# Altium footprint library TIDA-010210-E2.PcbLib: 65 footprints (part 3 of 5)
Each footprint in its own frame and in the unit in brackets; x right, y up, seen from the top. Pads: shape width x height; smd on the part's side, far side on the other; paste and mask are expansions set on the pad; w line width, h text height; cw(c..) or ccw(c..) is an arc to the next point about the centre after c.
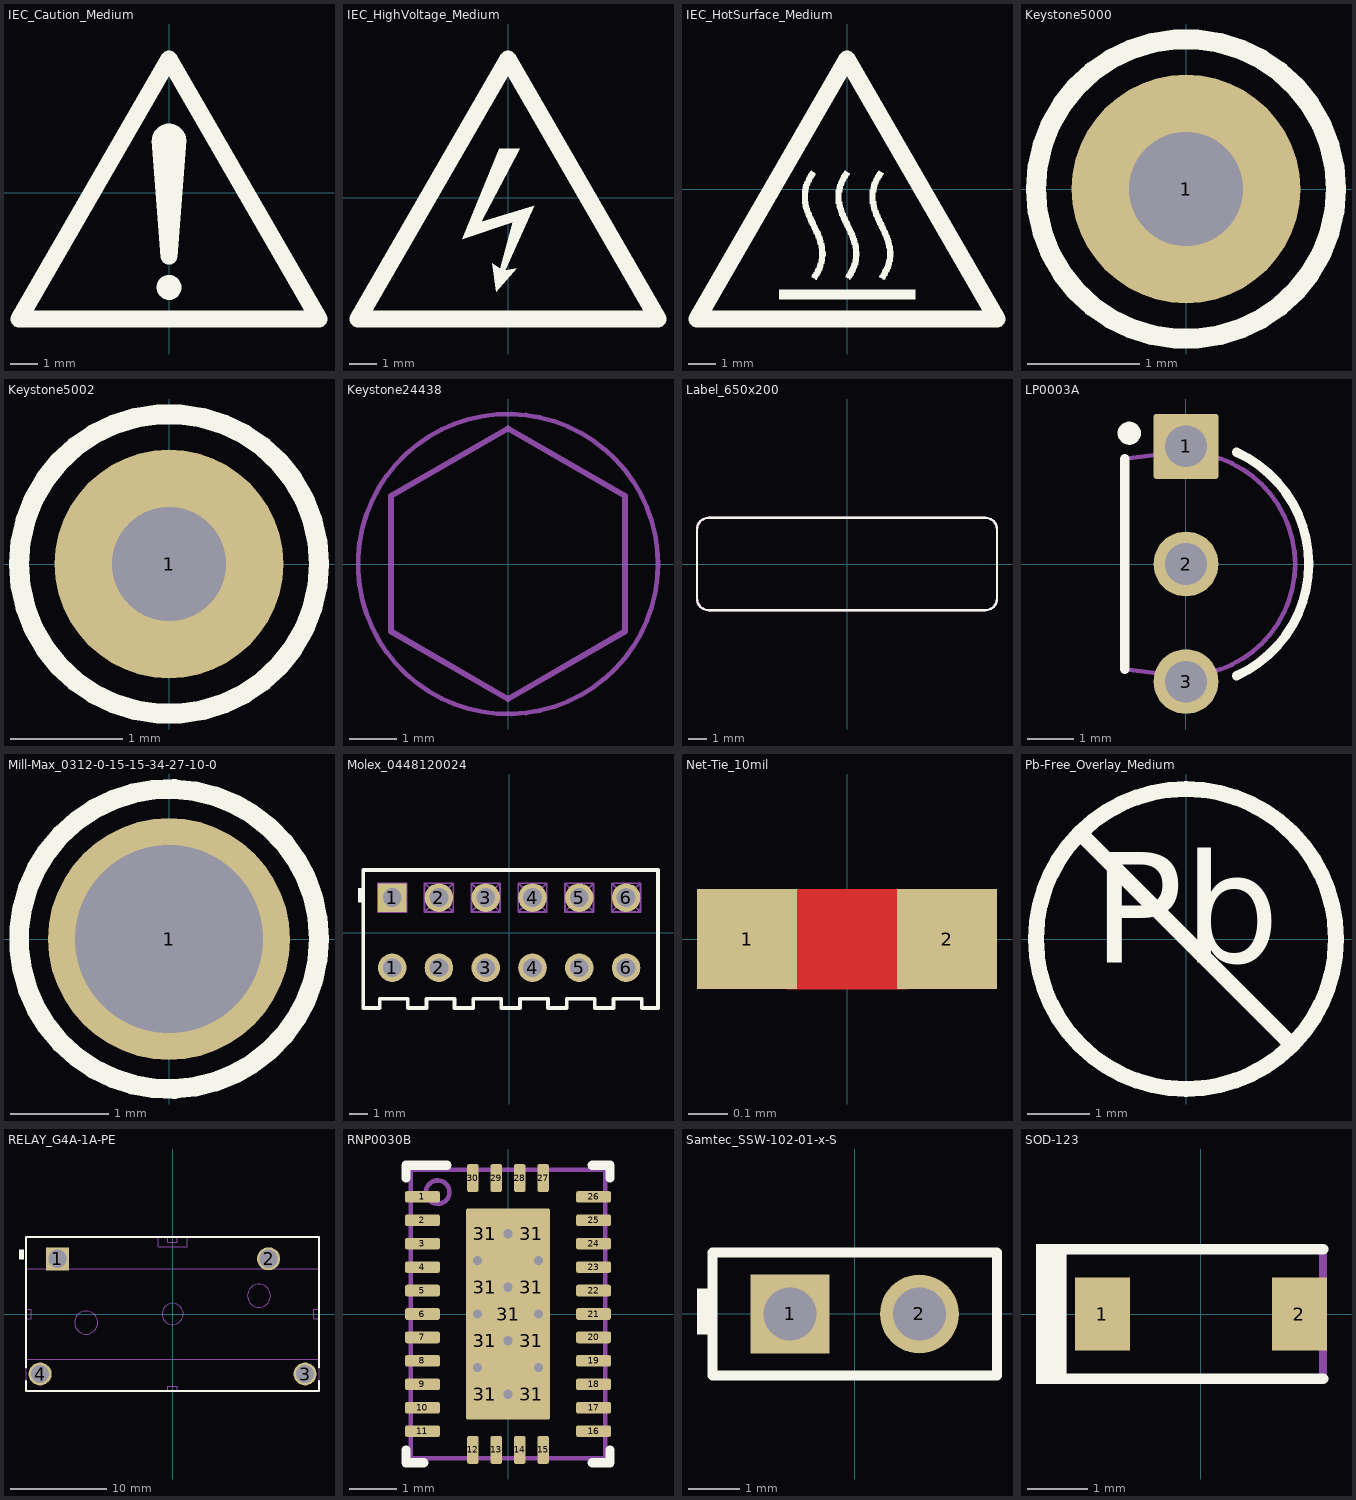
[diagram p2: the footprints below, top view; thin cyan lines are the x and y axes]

## IEC_Caution_Medium [mm]
height 27
Top Overlay:
  circle w0.457: c0,-3.48 r0.229
  circle w0.635: c0,1.905 r0.318
  circle w0.305: c0,-2.337 r0.152
  region: -0.635,1.93 0.635,1.93 0.305,-2.362 -0.305,-2.362
  lines w0.635: -5.512,-4.635 0,4.911 5.512,-4.635 -5.512,-4.635

## IEC_HighVoltage_Medium [mm]
height 27
Top Overlay:
  region: -0.33,1.803 0.432,1.803 -0.991,-0.889 0.965,-0.305 -0.102,-2.667 0.33,-2.591 -0.432,-3.454 -0.584,-2.413 -0.279,-2.616 0.178,-0.914 -1.676,-1.524
  lines w0.635: -5.512,-4.458 0,5.089 5.512,-4.458 -5.512,-4.458

## IEC_HotSurface_Medium [mm]
height 27
Top Overlay:
  drawing of 7 lines, arcs and shapes, not listed

## Keystone5000 [mil] "For Keystone 500x miniature loop terminals"
height 181.1
pads (1):
  round 80 hole 40: 1(0,0)
Top Overlay:
  circle w7: c0,0 r52.5
Mechanical 5:
  circle w3.94: c0,0 r52.5
  text ".Designator" at -92.97,-15 h18
3D body "Keystone_5000.stp": height 181.97, standoff -118.11, extent -49,-49 49.04,49.24

## Keystone5002 [mil] "For Keystone 500x miniature loop terminals"
height 181.1
pads (1):
  round 80 hole 40: 1(0,0)
Top Overlay:
  circle w7: c0,0 r52.5
Mechanical 5:
  circle w3.94: c0,0 r52.5
  text ".Designator" at -92.97,-15 h18
3D body "Keystone_5002.stp": height 181.97, standoff -118.11, extent -49,-49 49.04,49.23

## Keystone24438 [mil] "Standoff, Aluminium, M3x0.5mm, L 25 mm"
height 984.25
pads (1):
  round 1 on Mech3: 0(0,0)
Mechanical 5:
  circle w3.94: c0,0 r125.98
  lines w5: -98.43,-56.57 -98.43,57.09 0,113.91 98.43,57.09 98.43,-56.57 0,-113.39 -98.43,-56.57
  text ".Designator" at -73,-16 h40
3D body "Keystone_24438.stp": height 984.25, standoff 0, extent -98.43,-113.65 98.42,113.66

## Label_650x200 [mil] "Thermal Transfer Label"
height 1
pads (1):
  round 1 on Mech13: 0(0,0)
Top Overlay:
  lines w5: -325,-75 ccw(c-300,-75) -300,-100 300,-100 ccw(c300,-75) 325,-75 325,75 ccw(c300,75) 300,100 -300,100 ccw(c-300,75) -325,75 -325,-75
Mechanical 5:
  lines w5: -325,-75 ccw(c-300,-75) -300,-100 300,-100 ccw(c300,-75) 325,-75 325,75 ccw(c300,75) 300,100 -300,100 ccw(c-300,75) -325,75 -325,-75
  text ".Designator" at -60,-20 h40
3D body: height 1, standoff 0, extent -325.02,-100.02 325.02,100.02

## LP0003A [mm] "TO, Flat Index; 3 In-Line, Formed Axial Leads; Body Dia. 4.8mm; Leads 0.56 x 0.41 mm (max)"
height 9.33
pads (3):
  rrect7% 1.4x1.4 hole 0.9: 1(0,2.54)
  round 1.4 hole 0.9: 2(0,0) 3(0,-2.54)
Top Overlay:
  circle w0.25: c-1.225,2.825 r0.125
  lines w0.2: -1.325,-2.273 -1.325,2.273 ; 1.092,-2.415 ccw(c0,0) 1.092,2.415
Mechanical 5:
  lines w0.1: 0.195,-2.4 0.195,-2.722 0.195,-2.83 -0.185,-2.83 -0.185,-2.722 -0.185,-2.412 ; 0.195,2.4 0.195,2.722 0.195,2.83 -0.185,2.83 -0.185,2.722 -0.185,2.412 ; -0.185,-2.412 -1.325,-2.273 -1.325,2.273 -0.185,2.412 ; -0.185,-2.412 -0.055,-2.412 ccw(c-0.055,0) -0.055,2.412 -0.185,2.412
  text ".Designator" at -0.694,4.545 h0.89
3D body "LP0003B.stp": height 9.01, standoff -8.51, extent -1.333,-2.83 2.349,2.83

## Mill-Max_0312-0-15-15-34-27-10-0 [mm] "Pin Receptacle, .032-.046\" .075\" Dia, Gold, TH"
height 0.457
pads (1):
  round 2.45 hole 1.905: 1(0,0)
Top Overlay:
  circle w0.2: c0,0 r1.52
Mechanical 5:
  circle w0.1: c0,0 r1.156
  text ".Designator" at -0.725,-0.15 h0.4
3D body "0312-0-15-15-34-27-10-0.stp": height 0.46, standoff -4.78, extent -1.146,-1.153 1.156,1.154

## Molex_0448120024 [mm] "Receptacle, 2.54mm, 6x1, TH"
height 4.88
pads (12):
  round 1.55 hole 1.02: 1(-6.35,-1.905) 2(-3.81,-1.905) 2(-3.81,1.905) 3(-1.27,-1.905) 3(-1.27,1.905) 4(1.27,-1.905) 4(1.27,1.905) 5(3.81,-1.905) 5(3.81,1.905) 6(6.35,-1.905) 6(6.35,1.905)
  rect 1.55x1.55 hole 1.02: 1(-6.35,1.905)
Top Overlay:
  rectangle: -8.204,1.651 -7.95,2.413
  lines w0.2: -7.919,-4.089 -7.03,-4.089 -7.03,-3.589 -5.506,-3.589 -5.506,-4.089 -4.49,-4.089 -4.49,-3.589 -2.966,-3.589 -2.966,-4.089 -1.95,-4.089 -1.95,-3.589 -0.426,-3.589 -0.426,-4.089 0.59,-4.089 0.59,-3.589 2.114,-3.589 2.114,-4.089 3.13,-4.089 3.13,-3.589 4.654,-3.589 4.654,-4.089 5.67,-4.089 5.67,-3.589 7.194,-3.589 7.194,-4.089 8.083,-4.089 8.083,3.404 -7.919,3.404 -7.919,-4.089
Mechanical 5:
  drawing of 154 lines, arcs and shapes, not listed
  text ".Designator" at -1.524,-0.457 h1.02
3D body "448120024.stp": height 4.5, standoff -3.46, extent -7.919,-4.089 8.083,3.404

## Net-Tie_10mil [mil] "10mil net tie, no solder mask opening, no solder paste"
height 1062.99
pads (2):
  rect 10x10 smd paste-5 mask-5: 1(-10,0) 2(10,0)
Top Layer:
  region: -6,5 6,5 6,-5 -6,-5

## Pb-Free_Overlay_Medium [mm]
height 27
Top Overlay:
  circle w0.254: c0,0 r2.413
  lines w0.254: -1.706,1.706 1.706,-1.706
  text "Pb" at -1.505,-0.961 h3.05

## RELAY_G4A-1A-PE [mm] "THD, 4-Leads, Body 30.5x16mm, Height 26.8mm"
height 26.8
pads (4):
  rect 2.4x2.4 hole 1.9: 1(-12,5.75)
  round 2.4 hole 1.9: 2(10,5.75) 3(13.8,-6.25) 4(-13.8,-6.25)
Top Overlay:
  region: -16,6.7 -15.5,6.7 -15.5,5.7 -16,5.7
  lines w0.2: -15.25,-6.97 -15.25,-8 15.25,-8 15.25,-6.97 ; -15.25,-5.57 -15.25,8 15.25,8 15.25,-5.57
Mechanical 5:
  circle w0.1: c9,1.9 r1.2
  circle w0.1: c0,0 r1.1
  circle w0.1: c-9,-0.9 r1.2
  lines w0.1: -15.25,-4.7 15.25,-4.7 ; -15.25,4.7 15.25,4.7 ; -15.2,-0.5 -14.7,-0.5 -14.7,0.5 -15.2,0.5 ; -1.5,8 -1.5,7 1.5,7 1.5,8 ; -0.5,-8 -0.5,-7.5 0.5,-7.5 0.5,-8 ; -0.5,8 -0.5,7.5 0.5,7.5 0.5,8 ; 15.2,-0.5 14.7,-0.5 14.7,0.5 15.2,0.5 ; -15.25,-8 -15.25,8 15.25,8 15.25,-8 -15.25,-8 ; -14.2,-6.4 -13.4,-6.4 -13.4,-6.1 -14.2,-6.1 -14.2,-6.4 ; -12.75,5 -11.25,5 -11.25,6.5 -12.75,6.5 -12.75,5 ; 9.25,5 9.25,6.5 10.75,6.5 10.75,5 9.25,5 ; 13.4,-6.4 13.4,-6.1 14.2,-6.1 14.2,-6.4 13.4,-6.4
  text ".Designator" at -2.3,-0.4 h1.02
3D body: height 23.3, standoff 0, extent -15.25,-8 15.25,8
3D body: height 22.3, standoff 0, extent -1.5,7 1.5,8
3D body: height 0, standoff -3.5, extent 9.35,5 10.85,6.5
3D body: height 0, standoff -3.5, extent 13.4,-6.4 14.2,-6.1
3D body: height 0, standoff -3.5, extent -12.75,5 -11.25,6.5
3D body: height 0, standoff -3.5, extent -14.2,-6.4 -13.4,-6.1
3D body: height 0, standoff -0.5, extent 14.7,-0.5 15.2,0.5
3D body: height 0, standoff -0.5, extent -15.2,-0.5 -14.7,0.5
3D body: height 0, standoff -0.5, extent -0.5,-8 0.5,-7.5
3D body: height 0, standoff -0.5, extent -0.5,7.5 0.5,8
3D body: height 24, standoff 23.3, extent -10.199,-2.099 -7.801,0.299
3D body: height 24, standoff 23.3, extent 7.801,0.701 10.199,3.099
3D body: height 24, standoff 23.3, extent -1.099,-1.099 1.099,1.099
3D body: height 26.8, standoff 0, extent 9.1,-4.7 15.25,4.7
3D body: height 26.8, standoff 0, extent 0,-4.7 9.1,4.7
3D body: height 26.8, standoff 0, extent -9.1,-4.7 0,4.7
3D body: height 26.8, standoff 0, extent -15.25,-4.7 -9.1,4.7

## RNP0030B [mm] "QFN, 30-Leads, Body 6x4mm, Pitch 0.5mm, Thermal Pad 1.8x4.5mm"
height 0.8
pads (39):
  rrect40% 0.75x0.25 smd: 1(-1.825,2.5) 2(-1.825,2) 3(-1.825,1.5) 4(-1.825,1) 5(-1.825,0.5) 6(-1.825,0) 7(-1.825,-0.5) 8(-1.825,-1) 9(-1.825,-1.5) 10(-1.825,-2) 11(-1.825,-2.5) 16(1.825,-2.5) 17(1.825,-2) 18(1.825,-1.5) 19(1.825,-1) 20(1.825,-0.5) 21(1.825,0) 22(1.825,0.5) 23(1.825,1) 24(1.825,1.5) 25(1.825,2) 26(1.825,2.5)
  rrect40% 0.25x0.6 smd: 12(-0.75,-2.9) 13(-0.25,-2.9) 14(0.25,-2.9) 15(0.75,-2.9) 27(0.75,2.9) 28(0.25,2.9) 29(-0.25,2.9) 30(-0.75,2.9)
  rrect50% 0.8x0.94 on Top Paste: 31(-0.5,-1.71) 31(-0.5,-0.57) 31(-0.5,0.57) 31(-0.5,1.71) 31(0.5,-1.71) 31(0.5,-0.57) 31(0.5,0.57) 31(0.5,1.71)
  rrect5% 1.8x4.5 smd paste-3: 31(0,0)
via 0.65,-1.14 diameter 0.5 hole 0.2
via -0.65,-1.14 diameter 0.5 hole 0.2
via 0,-1.71 diameter 0.5 hole 0.2
via 0,-0.57 diameter 0.5 hole 0.2
via 0,0.57 diameter 0.5 hole 0.2
via 0,1.71 diameter 0.5 hole 0.2
via -0.65,1.14 diameter 0.5 hole 0.2
via 0.65,1.14 diameter 0.5 hole 0.2
via 0.65,0 diameter 0.5 hole 0.2
via -0.65,0 diameter 0.5 hole 0.2
Top Overlay:
  lines w0.2: -2.175,-2.9 -2.175,-3.175 -1.8,-3.175 ; -2.175,2.9 -2.175,3.175 -1.3,3.175 ; 1.8,-3.175 2.175,-3.175 2.175,-2.9 ; 1.8,3.175 2.175,3.175 2.175,2.9
Mechanical 5:
  circle w0.1: c-1.5,2.6 r0.25
  lines w0.1: -2.075,-3.075 2.075,-3.075 2.075,3.075 -2.075,3.075 -2.075,-3.075
  text ".Designator" at -1.8,-0.5 h1.02
3D body "RNP0030B.stp": height 0.8, standoff 0, extent -2,-3 2,3

## Samtec_SSW-102-01-x-S [mm] "Receptacle, 2x1, 2.54mm, TH"
height 8.64
pads (2):
  rect 1.55x1.55 hole 1.04: 1(-1.27,0)
  round 1.55 hole 1.04: 2(1.27,0)
Top Overlay:
  rectangle: -3.1,-0.4 -2.8,0.5
  lines w0.2: -2.794,-1.207 2.794,-1.207 2.794,1.206 -2.794,1.206 -2.794,-1.207
Mechanical 5:
  lines w0.1: -2.794,-1.207 -2.794,1.206 2.794,1.206 2.794,-1.207 -2.794,-1.207
  text ".Designator" at -1.524,-0.508 h1.02
3D body "SSW-102-01-T-S.stp": height 8.51, standoff -2.64, extent -2.788,-1.213 2.8,1.2

## SOD-123 [mm] "On Semi recommended land pattern"
height 1.35
pads (2):
  rect 0.915x1.22 smd: 1(-1.637,0) 2(1.637,0)
Top Overlay:
  rectangle: -2.743,-1.168 -2.235,1.168
  lines w0.178: -2.413,-1.079 2.032,-1.079 ; -2.413,1.079 2.032,1.079
Mechanical 5:
  rectangle: -2.743,-1.168 -2.235,1.168
  lines w0.127: -2.413,-1.079 2.032,-1.079 2.032,1.079 -2.413,1.079
  text ".Designator" at -1.956,-0.33 h0.76
3D body "SOD-123.stp": height 1.35, standoff 0, extent -1.932,-0.9 1.932,0.9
